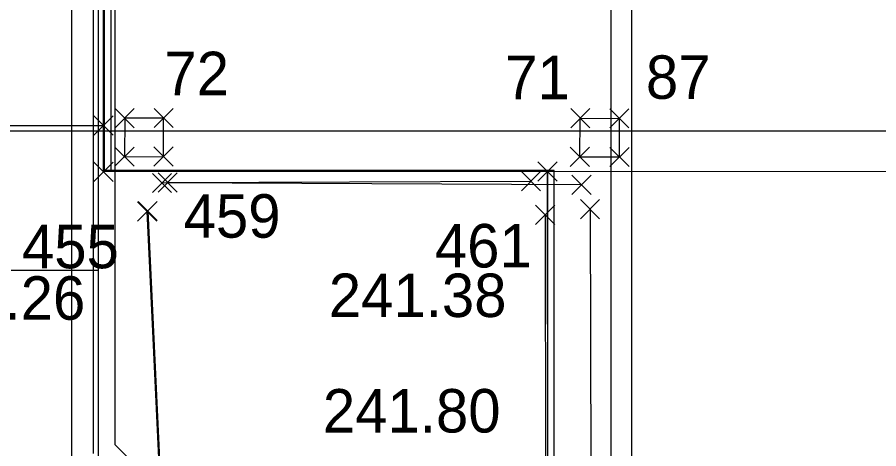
# Model space of a CAD drawing. Extents: x -264205 to -263659, y -1242401 to -1242060.
# Drawn here: x -263915.22 to -263905.31, y -1242199.53 to -1242194.57 of the extents above; entities that cross this region are included whole.
import ezdxf

# ---------------------------------------------------------------- set-up
doc = ezdxf.new("R2010")
doc.units = 0
for name, color, linetype in [('BOD_CISLO', 7, 'Continuous'), ('BOD_SYMBOL', 7, 'Continuous'), ('BOD_VYSKA', 7, 'Continuous'), ('KFA_SO_10-1_BETONOVE_STLPY', 7, 'Continuous'), ('KFA_SO_10-1_PLACHTY', 7, 'Continuous'), ('KFA_SO_10-1_STRECHY', 7, 'Continuous'), ('KFA_SO_10-1_TRIBUNA_A_HLAVNA_BUDOVA', 7, 'Continuous'), ('KFA_SO_10-1_TRIBUNA_A_OBVOD', 7, 'Continuous'), ('OBRUBNIKY_KOMUNIKACIE_PROJEKT', 7, 'Continuous'), ('OSI_STAVBY_KFA', 7, 'Continuous'), ('SITUACIA_DSP_2D', 7, 'Continuous')]:
    doc.layers.add(name, color=color, linetype=linetype)

msp = doc.modelspace()

# ---------------------------------------------------------------- linework, layer by layer
at = {"layer": 'BOD_SYMBOL'}
for p, q in [((-263914.0975, -1242195.8415), (-263913.8765, -1242195.6205)), ((-263913.8765, -1242195.8415), (-263914.0975, -1242195.6205)), ((-263913.6495, -1242195.8405), (-263913.4285, -1242195.6195)), ((-263913.4285, -1242195.8405), (-263913.6495, -1242195.6195)), ((-263908.8545, -1242195.8425), (-263908.6335, -1242195.6215)), ((-263908.6335, -1242195.8425), (-263908.8545, -1242195.6215)), ((-263908.4045, -1242195.8445), (-263908.1835, -1242195.6235)), ((-263908.1835, -1242195.8445), (-263908.4045, -1242195.6235)), ((-263914.3405, -1242195.9265), (-263914.1195, -1242195.7055)), ((-263914.1195, -1242195.9265), (-263914.3405, -1242195.7055)), ((-263914.0995, -1242196.2855), (-263913.8785, -1242196.0645)), ((-263913.8785, -1242196.2855), (-263914.0995, -1242196.0645)), ((-263913.6505, -1242196.2835), (-263913.4295, -1242196.0625)), ((-263913.4295, -1242196.2835), (-263913.6505, -1242196.0625)), ((-263908.8605, -1242196.2875), (-263908.6395, -1242196.0665)), ((-263908.6395, -1242196.2875), (-263908.8605, -1242196.0665)), ((-263908.4035, -1242196.2885), (-263908.1825, -1242196.0675)), ((-263908.1825, -1242196.2885), (-263908.4035, -1242196.0675)), ((-263914.3405, -1242196.4585), (-263914.1195, -1242196.2375)), ((-263914.1195, -1242196.4585), (-263914.3405, -1242196.2375)), ((-263914.3405, -1242196.4585), (-263914.1195, -1242196.2375)), ((-263914.1195, -1242196.4585), (-263914.3405, -1242196.2375)), ((-263909.2315, -1242196.4565), (-263909.0105, -1242196.2355)), ((-263909.0105, -1242196.4565), (-263909.2315, -1242196.2355)), ((-263909.4215, -1242196.5675), (-263909.2005, -1242196.3465)), ((-263909.2005, -1242196.5675), (-263909.4215, -1242196.3465)), ((-263913.6675, -1242196.5875), (-263913.4465, -1242196.3665)), ((-263913.4465, -1242196.5875), (-263913.6675, -1242196.3665)), ((-263913.6025, -1242196.5815), (-263913.3815, -1242196.3605)), ((-263913.3815, -1242196.5815), (-263913.6025, -1242196.3605)), ((-263908.8395, -1242196.6095), (-263908.6185, -1242196.3885)), ((-263908.6185, -1242196.6095), (-263908.8395, -1242196.3885)), ((-263913.8375, -1242196.9145), (-263913.6165, -1242196.6935)), ((-263913.6165, -1242196.9145), (-263913.8375, -1242196.6935)), ((-263913.8325, -1242196.9105), (-263913.6115, -1242196.6895)), ((-263913.6115, -1242196.9105), (-263913.8325, -1242196.6895)), ((-263909.2595, -1242196.9545), (-263909.0385, -1242196.7335)), ((-263909.0385, -1242196.9545), (-263909.2595, -1242196.7335)), ((-263908.7425, -1242196.8885), (-263908.5215, -1242196.6675)), ((-263908.5215, -1242196.8885), (-263908.7425, -1242196.6675))]:
    msp.add_line(p, q, dxfattribs=at)
at = {"layer": 'KFA_SO_10-1_BETONOVE_STLPY'}
for p, q in [((-263913.9867, -1242195.7311), (-263913.9892, -1242196.1752)), ((-263913.5389, -1242195.7299), (-263913.9867, -1242195.7311)), ((-263913.5401, -1242196.1728), (-263913.5389, -1242195.7299)), ((-263908.7505, -1242196.1769), (-263908.7437, -1242195.7318)), ((-263908.7437, -1242195.7318), (-263908.2941, -1242195.7342)), ((-263908.2929, -1242196.1781), (-263908.2941, -1242195.7342)), ((-263913.9892, -1242196.1752), (-263913.5401, -1242196.1728)), ((-263908.7505, -1242196.1769), (-263908.2929, -1242196.1781))]:
    msp.add_line(p, q, dxfattribs=at)
at = {"layer": 'KFA_SO_10-1_PLACHTY'}
for p, q in [((-263908.729, -1242196.499), (-263913.557, -1242196.477)), ((-263913.492, -1242196.471), (-263909.311, -1242196.457)), ((-263909.149, -1242196.844), (-263909.08, -1242226.989)), ((-263908.632, -1242196.778), (-263908.53, -1242226.78))]:
    msp.add_line(p, q, dxfattribs=at)
msp.add_lwpolyline([(-263912.238, -1242228.302), (-263912.237, -1242228.313), (-263913.727, -1242196.804), (-263913.722, -1242196.8)], close=True, dxfattribs=at)
at = {"layer": 'KFA_SO_10-1_STRECHY'}
msp.add_line((-263908.157, -1242227.179), (-263908.136, -1242101.59), dxfattribs=at)
at = {"layer": 'KFA_SO_10-1_TRIBUNA_A_HLAVNA_BUDOVA'}
for p, q in [((-263914.23, -1242196.348), (-263914.235, -1242132.417)), ((-263914.23, -1242196.348), (-263914.235, -1242132.417)), ((-263916.25, -1242195.816), (-263914.23, -1242195.8162)), ((-263903.251, -1242196.344), (-263914.23, -1242196.348))]:
    msp.add_line(p, q, dxfattribs=at)
msp.add_lwpolyline([(-263903.251, -1242196.344), (-263914.23, -1242196.348), (-263914.23, -1242196.348)], dxfattribs=at)
at = {"layer": 'KFA_SO_10-1_TRIBUNA_A_OBVOD'}
msp.add_lwpolyline([(-263909.114, -1242203.378), (-263909.121, -1242196.3461)], dxfattribs=at)
at = {"layer": 'OBRUBNIKY_KOMUNIKACIE_PROJEKT'}
for p, q in [((-263914.1428, -1242196.3327), (-263914.1428, -1242132.4327)), ((-263909.0427, -1242196.3327), (-263914.1428, -1242196.3327)), ((-263909.0427, -1242227.3822), (-263909.0427, -1242196.3327))]:
    msp.add_line(p, q, dxfattribs=at)
at = {"layer": 'OSI_STAVBY_KFA'}
for p, q in [((-263908.3928, -1242083.2372), (-263908.3928, -1242246.7072)), ((-263792.6528, -1242195.8822), (-263917.2628, -1242195.8822))]:
    msp.add_line(p, q, dxfattribs=at)
at = {"layer": 'SITUACIA_DSP_2D'}
for p, q in [((-263914.2178, -1242196.3322), (-263914.2178, -1242132.4322)), ((-263914.1428, -1242196.3327), (-263914.1428, -1242132.4327)), ((-263914.1002, -1242168.5213), (-263914.1002, -1242199.486)), ((-263914.3502, -1242168.6249), (-263914.3502, -1242199.5896)), ((-263914.6002, -1242168.7284), (-263914.6002, -1242199.6931)), ((-263914.2928, -1242175.4822), (-263914.2928, -1242210.4822)), ((-263909.1178, -1242196.3322), (-263914.2178, -1242196.3322)), ((-263909.0428, -1242196.3327), (-263914.1428, -1242196.3327)), ((-263909.1178, -1242203.3322), (-263909.1178, -1242196.3322)), ((-263909.0428, -1242227.3822), (-263909.0428, -1242196.3327)), ((-263914.2928, -1242197.4822), (-263915.2928, -1242197.4822)), ((-263914.1002, -1242199.486), (-263910.004, -1242203.5822))]:
    msp.add_line(p, q, dxfattribs=at)

# ---------------------------------------------------------------- texts
at = {"layer": 'BOD_CISLO'}
for s, p in [('72', (-263913.5296, -1242195.4671)), ('71', (-263909.6085, -1242195.513)), ('87', (-263907.9886, -1242195.5093)), ('459', (-263913.3088, -1242197.1064)), ('461', (-263910.4176, -1242197.4489)), ('455', (-263915.1695, -1242197.4583))]:
    msp.add_text(s, height=0.5, dxfattribs=at).set_placement(p)
at = {"layer": 'BOD_VYSKA'}
for s, p in [('246.26', (-263916.4852, -1242198.0503)), ('241.38', (-263911.6379, -1242198.0191)), ('241.80', (-263911.7061, -1242199.3475))]:
    msp.add_text(s, height=0.5, dxfattribs=at).set_placement(p)

doc.saveas('drawing.dxf')
